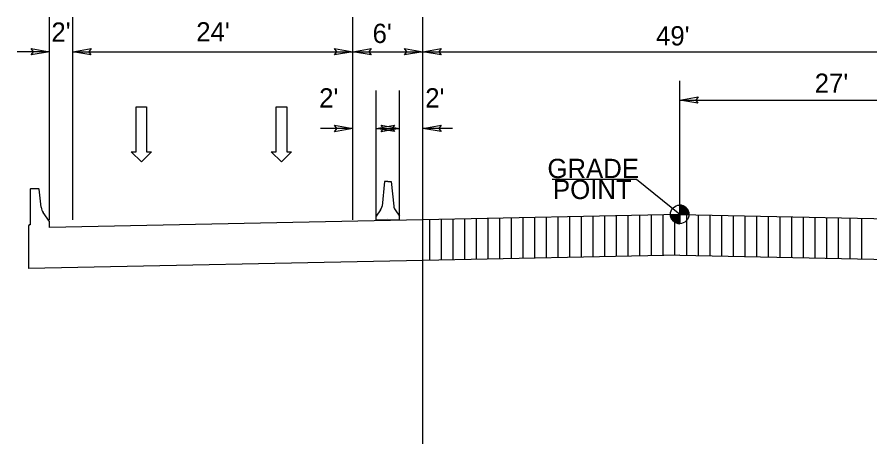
# Model space of a CAD drawing. Extents: x 2241081 to 2251104, y 658534 to 663427.
# Drawn here: x 2248154.1 to 2248482.9, y 658970.4 to 659134.9 of the extents above; entities that cross this region are included whole.
import ezdxf

# ---------------------------------------------------------------- set-up
doc = ezdxf.new("R2010")
doc.units = 0
for name, color, linetype in [('Prop Dimension', 7, 'Continuous'), ('Prop Dimension Text', 7, 'Continuous'), ('Prop Lane Arrow CELL', 7, 'Continuous'), ('Prop Roadway Bridge', 7, 'Continuous'), ('Typical Grade Point Symbol CELL', 7, 'Continuous'), ('Typical Median Barrier CELL', 7, 'Continuous'), ('Typical Terminator CELL', 7, 'Continuous'), ('Typical Text Grade Point CELL', 7, 'Continuous')]:
    doc.layers.add(name, color=color, linetype=linetype)

msp = doc.modelspace()

# ---------------------------------------------------------------- linework, layer by layer
at = {"layer": 'Prop Dimension'}
for p, q in [((2248166.6, 659056.8), (2248166.6, 659134.9)), ((2248175.6, 659056.8), (2248175.6, 659134.9)), ((2248283.6, 659069.31), (2248283.6, 659134.9)), ((2248310.6, 659056.8), (2248310.6, 659134.9)), ((2248292.6, 659069.31), (2248292.6, 659106.63)), ((2248301.6, 659069.31), (2248301.6, 659106.63))]:
    msp.add_line(p, q, dxfattribs=at)
at = {"layer": 'Prop Dimension Text'}
for p, q in [((2248283.6, 659056.8), (2248283.6, 659133.78)), ((2248310.6, 659057.36), (2248310.6, 659133.78)), ((2248310.6, 658970.42), (2248310.6, 659133.22)), ((2248166.6, 659121.54), (2248154.14, 659121.54)), ((2248175.6, 659121.54), (2248283.6, 659121.54)), ((2248175.6, 659121.54), (2248184.6, 659121.54)), ((2248283.6, 659121.54), (2248310.6, 659121.54)), ((2248310.6, 659121.54), (2248531.1, 659121.54)), ((2248409.6, 659058.86), (2248409.6, 659110.36)), ((2248409.6, 659102.89), (2248531.1, 659102.89)), ((2248292.6, 659057.36), (2248292.6, 659099.7)), ((2248301.6, 659057.36), (2248301.6, 659099.7)), ((2248283.6, 659091.98), (2248271.14, 659091.98)), ((2248292.6, 659091.98), (2248301.6, 659091.98)), ((2248322.02, 659091.98), (2248310.6, 659091.98)), ((2248313.29, 659041.19), (2248313.29, 659056.86)), ((2248317.79, 659041.29), (2248317.79, 659056.95)), ((2248322.29, 659041.38), (2248322.29, 659057.04)), ((2248326.79, 659041.47), (2248326.79, 659057.14)), ((2248331.29, 659041.57), (2248331.29, 659057.23)), ((2248335.79, 659041.66), (2248335.79, 659057.32)), ((2248340.29, 659041.75), (2248340.29, 659057.42)), ((2248344.79, 659041.85), (2248344.79, 659057.51)), ((2248349.29, 659041.94), (2248349.29, 659057.61)), ((2248353.79, 659042.03), (2248353.79, 659057.7)), ((2248358.29, 659042.13), (2248358.29, 659057.79)), ((2248362.79, 659042.22), (2248362.79, 659057.89)), ((2248367.29, 659042.32), (2248367.29, 659057.98)), ((2248371.79, 659042.41), (2248371.79, 659058.07)), ((2248376.29, 659042.5), (2248376.29, 659058.17)), ((2248380.79, 659042.6), (2248380.79, 659058.26)), ((2248385.29, 659042.69), (2248385.29, 659058.35)), ((2248389.79, 659042.78), (2248389.79, 659058.45)), ((2248394.29, 659042.88), (2248394.29, 659058.54)), ((2248398.79, 659042.97), (2248398.79, 659058.63)), ((2248403.29, 659043.06), (2248403.29, 659058.73)), ((2248407.79, 659043.16), (2248407.79, 659058.82)), ((2248412.29, 659043.14), (2248412.29, 659058.8)), ((2248416.79, 659043.05), (2248416.79, 659058.71)), ((2248421.29, 659042.95), (2248421.29, 659058.62)), ((2248425.79, 659042.86), (2248425.79, 659058.52)), ((2248430.29, 659042.77), (2248430.29, 659058.43)), ((2248434.79, 659042.67), (2248434.79, 659058.34)), ((2248439.29, 659042.58), (2248439.29, 659058.24)), ((2248443.79, 659042.48), (2248443.79, 659058.15)), ((2248448.29, 659042.39), (2248448.29, 659058.05)), ((2248452.79, 659042.3), (2248452.79, 659057.96)), ((2248457.29, 659042.2), (2248457.29, 659057.87)), ((2248461.79, 659042.11), (2248461.79, 659057.77)), ((2248466.29, 659042.02), (2248466.29, 659057.68)), ((2248470.79, 659041.92), (2248470.79, 659057.59)), ((2248475.29, 659041.83), (2248475.29, 659057.49)), ((2248479.79, 659041.74), (2248479.79, 659057.4))]:
    msp.add_line(p, q, dxfattribs=at)
at = {"layer": 'Prop Lane Arrow CELL'}
for p, q in [((2248200, 659082.96), (2248200, 659100.33)), ((2248200, 659100.33), (2248204.09, 659100.33)), ((2248204.09, 659100.33), (2248204.09, 659082.96)), ((2248254, 659082.96), (2248254, 659100.33)), ((2248254, 659100.33), (2248258.09, 659100.33)), ((2248258.09, 659100.33), (2248258.09, 659082.96)), ((2248202.1, 659079.06), (2248198.14, 659082.96)), ((2248198.14, 659082.96), (2248200, 659082.96)), ((2248205.95, 659082.96), (2248202.1, 659079.06)), ((2248204.09, 659082.96), (2248205.95, 659082.96)), ((2248256.1, 659079.06), (2248252.14, 659082.96)), ((2248252.14, 659082.96), (2248254, 659082.96)), ((2248259.95, 659082.96), (2248256.1, 659079.06)), ((2248258.09, 659082.96), (2248259.95, 659082.96))]:
    msp.add_line(p, q, dxfattribs=at)
at = {"layer": 'Prop Roadway Bridge'}
for p, q in [((2248159.36, 659068.75), (2248159.19, 659068.59)), ((2248159.19, 659068.59), (2248159.19, 659054.81)), ((2248162.52, 659068.75), (2248159.36, 659068.75)), ((2248162.7, 659068.57), (2248162.52, 659068.75)), ((2248163.43, 659061.6), (2248162.7, 659068.57)), ((2248166.6, 659056.12), (2248164.2, 659059.55)), ((2248310.6, 659056.8), (2248166.6, 659053.81)), ((2248409.6, 659058.86), (2248310.6, 659056.8)), ((2248409.6, 659058.86), (2248526.6, 659056.43)), ((2248158.87, 659054.81), (2248158.54, 659054.49)), ((2248158.54, 659054.49), (2248158.54, 659052.2)), ((2248159.19, 659054.81), (2248158.87, 659054.81)), ((2248166.6, 659053.81), (2248166.6, 659056.12)), ((2248158.54, 659052.2), (2248158.54, 659037.97)), ((2248310.6, 659041.14), (2248158.54, 659037.97)), ((2248409.6, 659043.2), (2248310.6, 659041.14)), ((2248409.6, 659043.2), (2248526.6, 659040.76))]:
    msp.add_line(p, q, dxfattribs=at)
msp.add_arc((2248167.76, 659062.05), 4.36, 186.011, 214.9912, dxfattribs=at)
at = {"layer": 'Typical Grade Point Symbol CELL'}
for p, q in [((2248409.6, 659058.86), (2248392.91, 659072.31)), ((2248409.61, 659062.44), (2248409.6, 659058.86)), ((2248409.6, 659058.86), (2248409.61, 659062.44)), ((2248406.02, 659058.86), (2248409.6, 659058.86)), ((2248409.6, 659058.86), (2248409.6, 659055.28)), ((2248413.18, 659058.86), (2248409.6, 659058.86))]:
    msp.add_line(p, q, dxfattribs=at)
for points in [[(2248409.65, 659058.86), (2248409.65, 659062.44), (2248409.65, 659062.44)], [(2248409.73, 659058.86), (2248409.73, 659062.44)], [(2248409.8, 659058.86), (2248409.8, 659062.43)], [(2248409.87, 659058.86), (2248409.87, 659062.43)], [(2248409.94, 659058.86), (2248409.94, 659062.42)], [(2248410.01, 659058.86), (2248410.01, 659062.42)], [(2248410.08, 659058.86), (2248410.08, 659062.41)], [(2248410.16, 659058.86), (2248410.16, 659062.39)], [(2248410.23, 659058.86), (2248410.23, 659062.38)], [(2248410.3, 659058.86), (2248410.3, 659062.37)], [(2248410.37, 659058.86), (2248410.37, 659062.35)], [(2248410.44, 659058.86), (2248410.44, 659062.34)], [(2248410.51, 659058.86), (2248410.51, 659062.32)], [(2248410.59, 659058.86), (2248410.59, 659062.3)], [(2248410.66, 659058.86), (2248410.66, 659062.28)], [(2248410.73, 659058.86), (2248410.73, 659062.26)], [(2248410.8, 659058.86), (2248410.8, 659062.23)], [(2248410.87, 659058.86), (2248410.87, 659062.21)], [(2248410.94, 659058.86), (2248410.94, 659062.18)], [(2248411.01, 659058.86), (2248411.01, 659062.15)], [(2248411.09, 659058.86), (2248411.09, 659062.11)], [(2248411.16, 659058.86), (2248411.16, 659062.08)], [(2248411.23, 659058.86), (2248411.23, 659062.05)], [(2248411.3, 659058.86), (2248411.3, 659062.01)], [(2248411.37, 659058.86), (2248411.37, 659061.97)], [(2248411.44, 659058.86), (2248411.44, 659061.93)], [(2248411.52, 659058.86), (2248411.52, 659061.88)], [(2248411.59, 659058.86), (2248411.59, 659061.84)], [(2248411.66, 659058.86), (2248411.66, 659061.79)], [(2248411.73, 659058.86), (2248411.73, 659061.74)], [(2248411.8, 659058.86), (2248411.8, 659061.68)], [(2248411.87, 659058.86), (2248411.87, 659061.63)], [(2248411.95, 659058.86), (2248411.95, 659061.56)], [(2248412.02, 659058.86), (2248412.02, 659061.5)], [(2248412.09, 659058.86), (2248412.09, 659061.44)], [(2248412.16, 659058.86), (2248412.16, 659061.37)], [(2248412.23, 659058.86), (2248412.23, 659061.29)], [(2248412.3, 659058.86), (2248412.3, 659061.21)], [(2248412.38, 659058.86), (2248412.38, 659061.12)], [(2248412.45, 659058.86), (2248412.45, 659061.03)], [(2248412.52, 659058.86), (2248412.52, 659060.94)], [(2248412.59, 659058.86), (2248412.59, 659060.83)], [(2248412.66, 659058.86), (2248412.66, 659060.72)], [(2248412.73, 659058.86), (2248412.73, 659060.59)], [(2248412.81, 659058.86), (2248412.81, 659060.46)], [(2248412.88, 659058.86), (2248412.88, 659060.31)], [(2248412.95, 659058.86), (2248412.95, 659060.14)], [(2248406.06, 659058.35), (2248406.06, 659058.86)], [(2248406.13, 659057.98), (2248406.13, 659058.86)], [(2248406.2, 659057.74), (2248406.2, 659058.86)], [(2248406.27, 659057.54), (2248406.27, 659058.86)], [(2248406.34, 659057.37), (2248406.34, 659058.86)], [(2248406.42, 659057.22), (2248406.42, 659058.86)], [(2248406.49, 659057.09), (2248406.49, 659058.86)], [(2248406.56, 659056.97), (2248406.56, 659058.86)], [(2248406.63, 659056.86), (2248406.63, 659058.86)], [(2248406.7, 659056.76), (2248406.7, 659058.86)], [(2248406.77, 659056.66), (2248406.77, 659058.86)], [(2248406.85, 659056.58), (2248406.85, 659058.86)], [(2248406.92, 659056.49), (2248406.92, 659058.86)], [(2248406.99, 659056.41), (2248406.99, 659058.86)], [(2248407.06, 659056.34), (2248407.06, 659058.86)], [(2248407.13, 659056.27), (2248407.13, 659058.86)], [(2248407.2, 659056.2), (2248407.2, 659058.86)], [(2248407.27, 659056.14), (2248407.27, 659058.86)], [(2248407.35, 659056.07), (2248407.35, 659058.86)], [(2248407.42, 659056.02), (2248407.42, 659058.86)], [(2248407.49, 659055.97), (2248407.49, 659058.86)], [(2248407.56, 659055.92), (2248407.56, 659058.86)], [(2248407.63, 659055.87), (2248407.63, 659058.86)], [(2248407.7, 659055.82), (2248407.7, 659058.86)], [(2248407.78, 659055.78), (2248407.78, 659058.86)], [(2248407.85, 659055.74), (2248407.85, 659058.86)], [(2248407.92, 659055.7), (2248407.92, 659058.86)], [(2248407.99, 659055.66), (2248407.99, 659058.86)], [(2248408.06, 659055.63), (2248408.06, 659058.86)], [(2248408.13, 659055.6), (2248408.13, 659058.86)], [(2248408.21, 659055.56), (2248408.21, 659058.86)], [(2248408.28, 659055.53), (2248408.28, 659058.86)], [(2248408.35, 659055.5), (2248408.35, 659058.86)], [(2248408.42, 659055.48), (2248408.42, 659058.86)], [(2248408.49, 659055.45), (2248408.49, 659058.86)], [(2248408.56, 659055.43), (2248408.56, 659058.86)], [(2248408.64, 659055.41), (2248408.64, 659058.86)], [(2248408.71, 659055.39), (2248408.71, 659058.86)], [(2248408.78, 659055.37), (2248408.78, 659058.86)], [(2248408.85, 659055.36), (2248408.85, 659058.86)], [(2248408.92, 659055.34), (2248408.92, 659058.86)], [(2248408.99, 659055.33), (2248408.99, 659058.86)], [(2248409.07, 659055.32), (2248409.07, 659058.86)], [(2248409.14, 659055.31), (2248409.14, 659058.86)], [(2248409.21, 659055.3), (2248409.21, 659058.86)], [(2248409.28, 659055.29), (2248409.28, 659058.86)], [(2248409.35, 659055.29), (2248409.35, 659058.86)], [(2248409.42, 659055.29), (2248409.42, 659058.86)], [(2248409.49, 659055.28), (2248409.49, 659058.86)], [(2248409.57, 659055.28), (2248409.57, 659055.28), (2248409.57, 659058.86)], [(2248413.02, 659058.86), (2248413.02, 659059.93)], [(2248413.09, 659058.86), (2248413.09, 659059.67)], [(2248413.16, 659058.86), (2248413.16, 659059.25)]]:
    msp.add_lwpolyline(points, dxfattribs=at)
msp.add_circle((2248409.6, 659058.86), 3.58, dxfattribs=at)
for start, end in [(359.9905, 89.9905), (179.9905, 269.9905)]:
    msp.add_arc((2248409.6, 659058.86), 3.58, start, end, dxfattribs=at)
at = {"layer": 'Typical Median Barrier CELL'}
for p, q in [((2248295.86, 659071.53), (2248294.86, 659062.08)), ((2248297.1, 659071.53), (2248295.86, 659071.53)), ((2248297.1, 659071.53), (2248298.34, 659071.53)), ((2248298.34, 659071.53), (2248299.34, 659062.08)), ((2248294.31, 659060.63), (2248292.6, 659058.18)), ((2248299.89, 659060.63), (2248301.6, 659058.18)), ((2248292.6, 659056.63), (2248292.6, 659058.18)), ((2248297.1, 659057.25), (2248297.1, 659057.25)), ((2248301.6, 659056.63), (2248301.6, 659058.18)), ((2248301.6, 659056.63), (2248292.6, 659056.63))]:
    msp.add_line(p, q, dxfattribs=at)
for centre, start, end in [((2248291.77, 659062.41), 325.0062, 353.9447), ((2248302.43, 659062.41), 186.0552, 214.996)]:
    msp.add_arc(centre, 3.1, start, end, dxfattribs=at)
at = {"layer": 'Typical Terminator CELL'}
for points in [[(2248159.57, 659122.75), (2248166.6, 659121.54), (2248159.53, 659120.29), (2248160.43, 659121.54)], [(2248182.63, 659120.33), (2248175.6, 659121.54), (2248182.67, 659122.79), (2248181.77, 659121.54)], [(2248276.57, 659122.75), (2248283.6, 659121.54), (2248276.53, 659120.29), (2248277.43, 659121.54)], [(2248290.63, 659120.33), (2248283.6, 659121.54), (2248290.67, 659122.79), (2248289.77, 659121.54)], [(2248303.57, 659122.75), (2248310.6, 659121.54), (2248303.53, 659120.29), (2248304.43, 659121.54)], [(2248317.63, 659120.33), (2248310.6, 659121.54), (2248317.67, 659122.79), (2248316.77, 659121.54)], [(2248416.63, 659101.68), (2248409.6, 659102.89), (2248416.67, 659104.14), (2248415.77, 659102.89)], [(2248276.57, 659093.19), (2248283.6, 659091.98), (2248276.53, 659090.73), (2248277.43, 659091.98)], [(2248299.63, 659090.77), (2248292.6, 659091.98), (2248299.67, 659093.23), (2248298.77, 659091.98)], [(2248294.57, 659093.19), (2248301.6, 659091.98), (2248294.53, 659090.73), (2248295.43, 659091.98)], [(2248317.63, 659090.77), (2248310.6, 659091.98), (2248317.67, 659093.23), (2248316.77, 659091.98)]]:
    msp.add_lwpolyline(points, close=True, dxfattribs=at)
at = {"layer": 'Typical Text Grade Point CELL'}
msp.add_line((2248392.91, 659072.31), (2248360.4, 659072.31), dxfattribs=at)

# ---------------------------------------------------------------- texts
at = {"layer": 'Prop Dimension Text'}
for s, p in [("2'", (2248167.38, 659125.4)), ("24'", (2248223.22, 659125.5)), ("6'", (2248291.2, 659124.91)), ("49'", (2248400.48, 659123.97)), ("27'", (2248461.65, 659105.71)), ("2'", (2248270.6, 659100.05)), ("2'", (2248311.5, 659100.05))]:
    msp.add_text(s, height=7.425, rotation=359.9999, dxfattribs=at).set_placement(p)
at = {"layer": 'Typical Text Grade Point CELL'}
for s, p in [('GRADE', (2248358.61, 659072.87)), ('POINT', (2248360.75, 659064.77))]:
    msp.add_text(s, height=7.425, rotation=359.9999, dxfattribs=at).set_placement(p)

doc.saveas('drawing.dxf')
